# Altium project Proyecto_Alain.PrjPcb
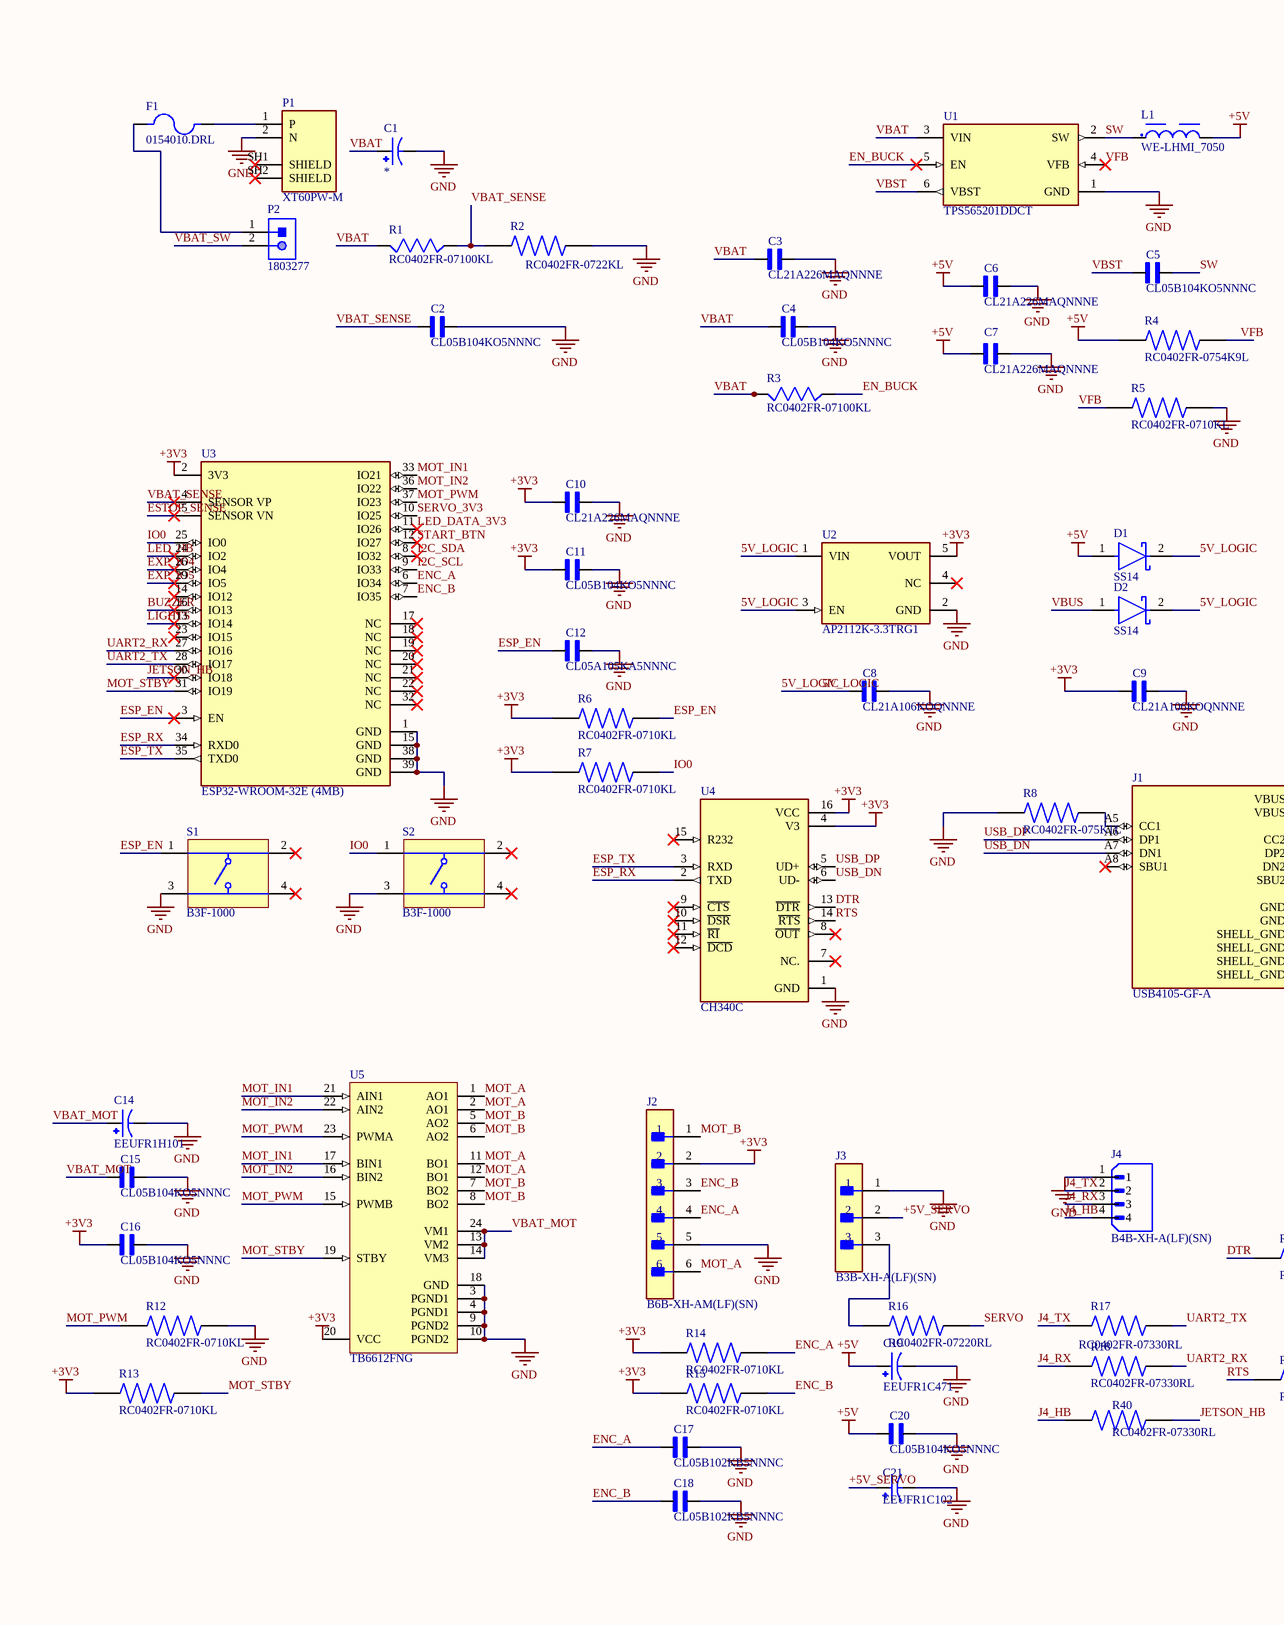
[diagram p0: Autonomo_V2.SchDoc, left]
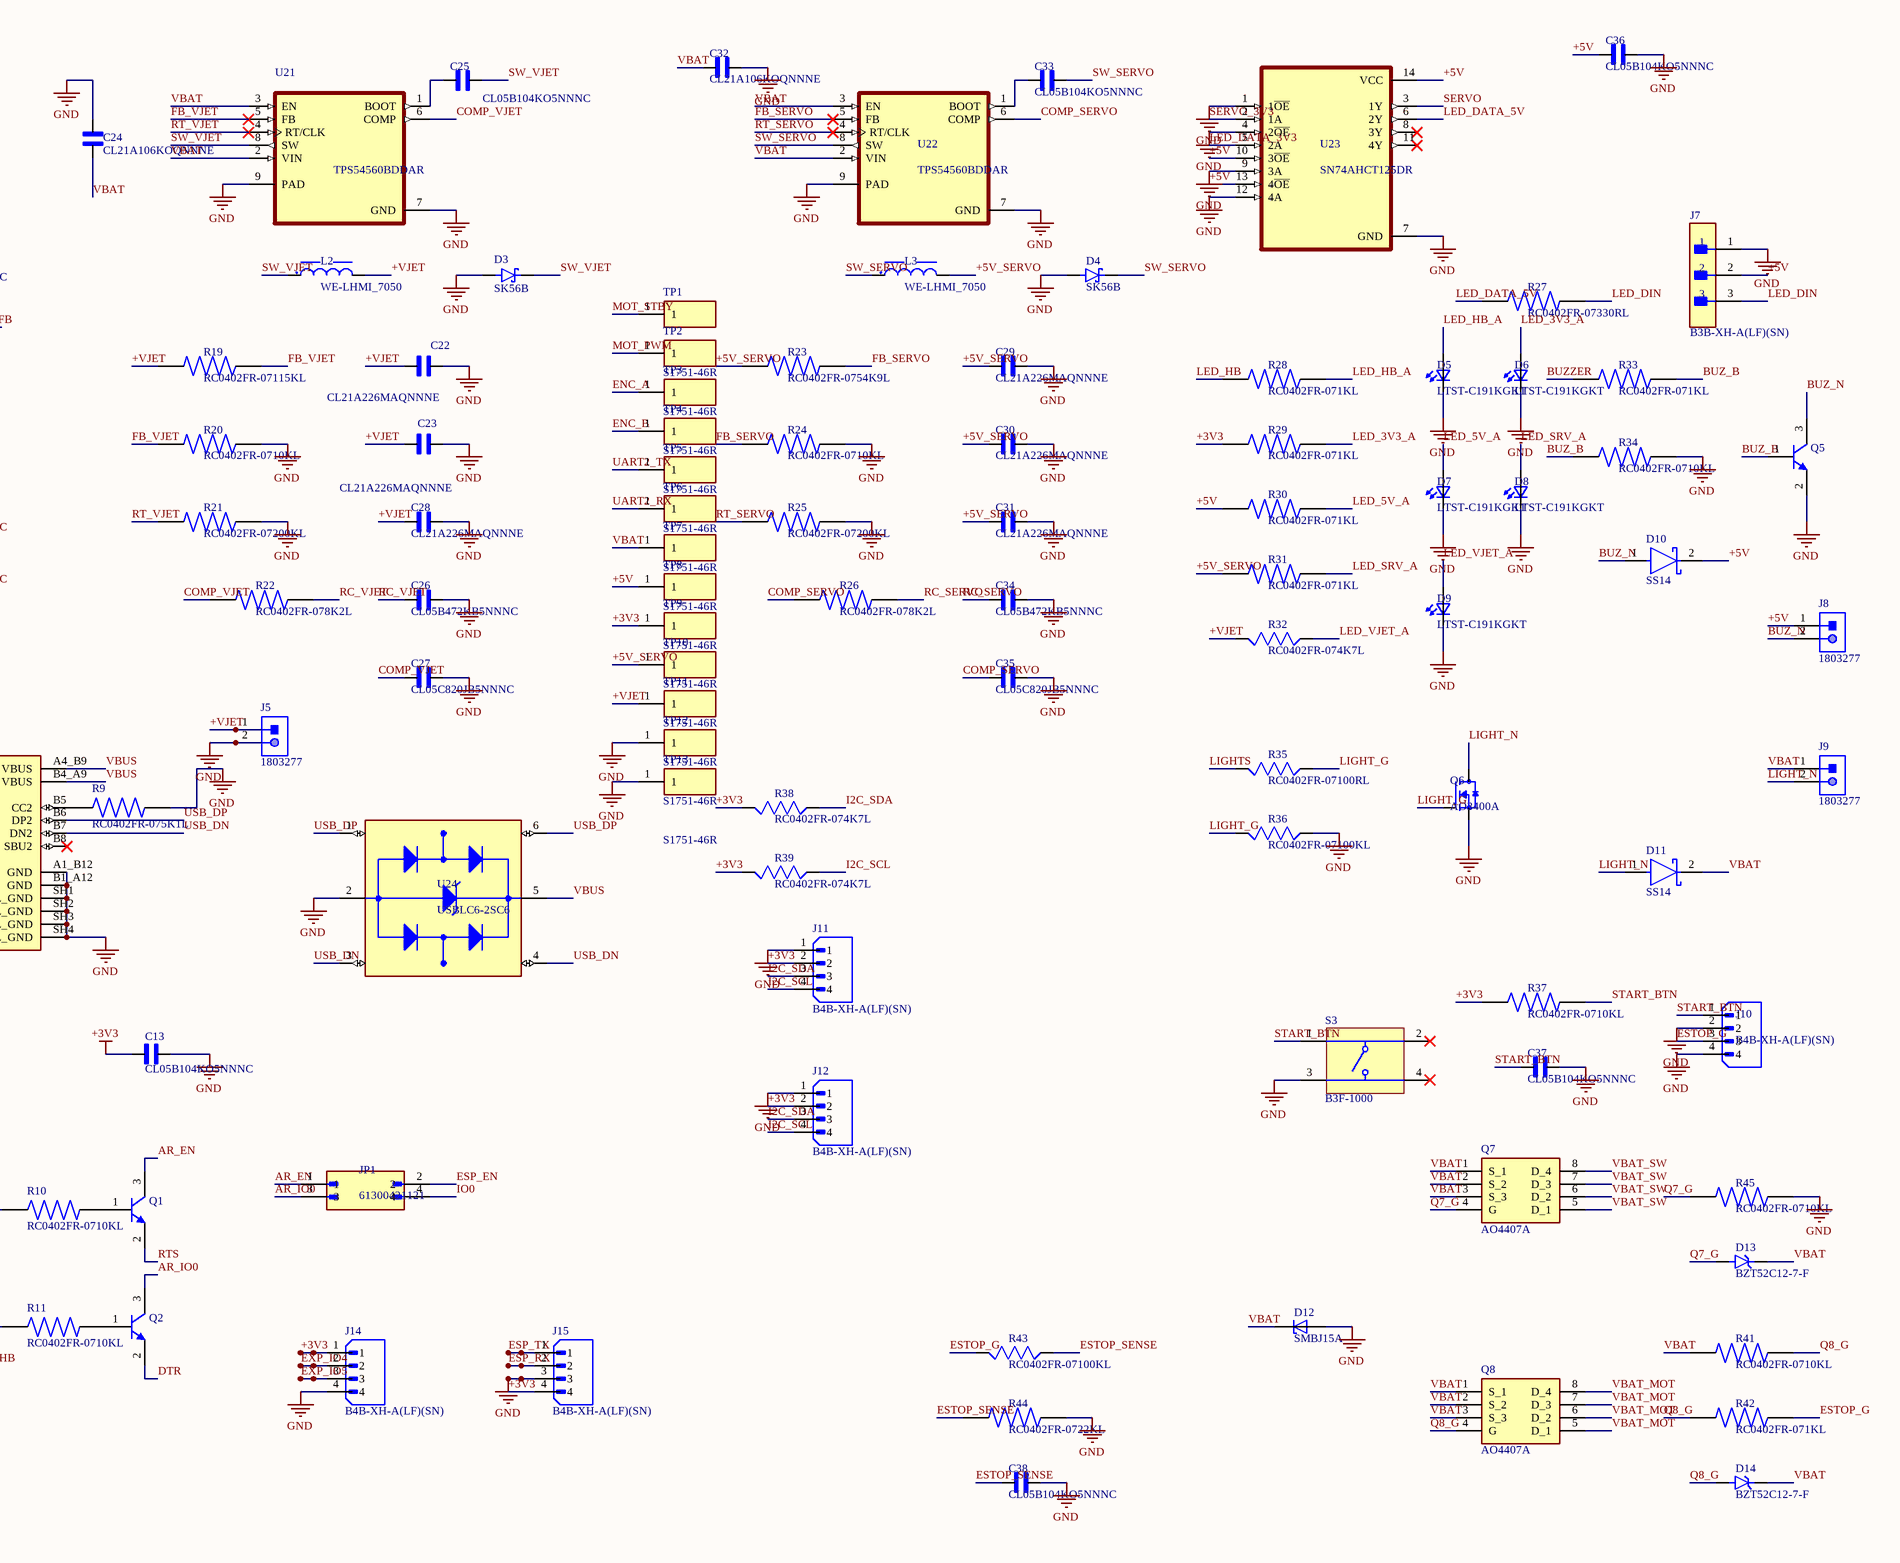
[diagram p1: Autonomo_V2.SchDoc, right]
1 sheet, 148 parts. Net scope: global (net labels, ports and power ports of the same name join across sheets).
Board file: Autonomo_V2.PcbDoc

## Sheet Autonomo_V2.SchDoc
size 609 x 304 mm; SheetNumber: 1; SheetTotal: 1

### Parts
C1  EEUFR1H471  [CAPPRD500W60D1250H2000]  (value not drawn)
C2  CL05B104KO5NNNC  [CAPC1005X55N]
C3  CL21A226MAQNNNE  [CAPC2012X140N]
C4  CL05B104KO5NNNC  [CAPC1005X55N]
C5  CL05B104KO5NNNC  [CAPC1005X55N]
C6  CL21A226MAQNNNE  [CAPC2012X140N]
C7  CL21A226MAQNNNE  [CAPC2012X140N]
C8  CL21A106KOQNNNE  [CAPC2012X140N]
C9  CL21A106KOQNNNE  [CAPC2012X140N]
C10  CL21A226MAQNNNE  [CAPC2012X140N]
C11  CL05B104KO5NNNC  [CAPC1005X55N]
C12  CL05A105KA5NNNC  [CAPC1005X55N]
C13  CL05B104KO5NNNC  [CAPC1005X55N]
C14  EEUFR1H101  [CAPPRD350W60D800H1150]
C15  CL05B104KO5NNNC  [CAPC1005X55N]
C16  CL05B104KO5NNNC  [CAPC1005X55N]
C17  CL05B102KB5NNNC  [CAPC1005X55N]
C18  CL05B102KB5NNNC  [CAPC1005X55N]
C19  EEUFR1C471  [CAPPRD350W60D800H1150]
C20  CL05B104KO5NNNC  [CAPC1005X55N]
C21  EEUFR1C102  [CAPPRD500W60D1000H1600]
C22  CL21A226MAQNNNE  [CAPC2012X140N]
C23  CL21A226MAQNNNE  [CAPC2012X140N]
C24  CL21A106KOQNNNE  [CAPC2012X140N]
C25  CL05B104KO5NNNC  [CAPC1005X55N]
C26  CL05B472KB5NNNC  [CAPC1005X55N]
C27  CL05C820JB5NNNC  [CAPC1005X55N]
C28  CL21A226MAQNNNE  [CAPC2012X140N]
C29  CL21A226MAQNNNE  [CAPC2012X140N]
C30  CL21A226MAQNNNE  [CAPC2012X140N]
C31  CL21A226MAQNNNE  [CAPC2012X140N]
C32  CL21A106KOQNNNE  [CAPC2012X140N]
C33  CL05B104KO5NNNC  [CAPC1005X55N]
C34  CL05B472KB5NNNC  [CAPC1005X55N]
C35  CL05C820JB5NNNC  [CAPC1005X55N]
C36  CL05B104KO5NNNC  [CAPC1005X55N]
C37  CL05B104KO5NNNC  [CAPC1005X55N]
C38  CL05B104KO5NNNC  [CAPC1005X55N]
D1  SS14  [FP-403AE-MFG]
D2  SS14  [FP-403AE-MFG]
D3  SK56B  [DIO_SK56B]
D4  SK56B  [DIO_SK56B]
D5  LTST-C191KGKT  [0603]
D6  LTST-C191KGKT  [0603]
D7  LTST-C191KGKT  [0603]
D8  LTST-C191KGKT  [0603]
D9  LTST-C191KGKT  [0603]
D10  SS14  [FP-403AE-MFG]
D11  SS14  [FP-403AE-MFG]
D12  SMBJ15A  [DIOM4336X265N]
D13  BZT52C12-7-F  [DIO_BZT52C12-7-F]
D14  BZT52C12-7-F  [DIO_BZT52C12-7-F]
F1  0154010.DRL  [FUSE_0154010.DRL]
J1  USB4105-GF-A  [GCT_USB4105-GF-A]
J2  B6B-XH-AM(LF)(SN)  [FP-B6B-XH-AM_LF_SN-MFG]
J3  B3B-XH-A(LF)(SN)  [FP-B3B-XH-A_LF_SN-MFG]
J4  B4B-XH-A(LF)(SN)  [JST_B4B-XH-A(LF)(SN)]
J5  1803277  [PHOE-1803277_V]
J7  B3B-XH-A(LF)(SN)  [FP-B3B-XH-A_LF_SN-MFG]
J8  1803277  [PHOE-1803277_V]
J9  1803277  [PHOE-1803277_V]
J10  B4B-XH-A(LF)(SN)  [JST_B4B-XH-A(LF)(SN)]
J11  B4B-XH-A(LF)(SN)  [JST_B4B-XH-A(LF)(SN)]
J12  B4B-XH-A(LF)(SN)  [JST_B4B-XH-A(LF)(SN)]
J14  B4B-XH-A(LF)(SN)  [JST_B4B-XH-A(LF)(SN)]
J15  B4B-XH-A(LF)(SN)  [JST_B4B-XH-A(LF)(SN)]
JP1  61300421121  [WURTH_61300421121]
L1  WE-LHMI_7050  [WE-LHMI_7050]
L2  WE-LHMI_7050  [WE-LHMI_7050]
L3  WE-LHMI_7050  [WE-LHMI_7050]
P1  XT60PW-M  [AMASS_XT60PW-M]
P2  1803277  [PHOE-1803277_V]
Q1  MMBT3904  [FAIR-SOT23-3_V]  (value not drawn)
Q2  MMBT3904  [FAIR-SOT23-3_V]  (value not drawn)
Q5  MMBT3904  [FAIR-SOT23-3_V]  (value not drawn)
Q6  AO3400A  [SOT95P280X125-3N]
Q7  AO4407A  [SOIC127P600X175-8N]
Q8  AO4407A  [SOIC127P600X175-8N]
R1  RC0402FR-07100KL  [RESC1005X40]
R2  RC0402FR-0722KL  [RESC1005X40N]
R3  RC0402FR-07100KL  [RESC1005X40]
R4  RC0402FR-0754K9L  [RESC1005X40N]
R5  RC0402FR-0710KL  [RESC1005X40N]
R6  RC0402FR-0710KL  [RESC1005X40N]
R7  RC0402FR-0710KL  [RESC1005X40N]
R8  RC0402FR-075K1L  [RESC1005X40N]
R9  RC0402FR-075K1L  [RESC1005X40N]
R10  RC0402FR-0710KL  [RESC1005X40N]
R11  RC0402FR-0710KL  [RESC1005X40N]
R12  RC0402FR-0710KL  [RESC1005X40N]
R13  RC0402FR-0710KL  [RESC1005X40N]
R14  RC0402FR-0710KL  [RESC1005X40N]
R15  RC0402FR-0710KL  [RESC1005X40N]
R16  RC0402FR-07220RL  [RESC1005X40N]
R17  RC0402FR-07330RL  [RESC1005X40N]
R18  RC0402FR-07330RL  [RESC1005X40N]
R19  RC0402FR-07115KL  [RESC1005X40N]
R20  RC0402FR-0710KL  [RESC1005X40N]
R21  RC0402FR-07200KL  [RESC1005X40N]
R22  RC0402FR-078K2L  [RESC1005X40N]
R23  RC0402FR-0754K9L  [RESC1005X40N]
R24  RC0402FR-0710KL  [RESC1005X40N]
R25  RC0402FR-07200KL  [RESC1005X40N]
R26  RC0402FR-078K2L  [RESC1005X40N]
R27  RC0402FR-07330RL  [RESC1005X40N]
R28  RC0402FR-071KL  [RESC1005X40N]
R29  RC0402FR-071KL  [RESC1005X40N]
R30  RC0402FR-071KL  [RESC1005X40N]
R31  RC0402FR-071KL  [RESC1005X40N]
R32  RC0402FR-074K7L  [RESC1005X40]
R33  RC0402FR-071KL  [RESC1005X40N]
R34  RC0402FR-0710KL  [RESC1005X40N]
R35  RC0402FR-07100RL  [RESC1005X40]
R36  RC0402FR-07100KL  [RESC1005X40]
R37  RC0402FR-0710KL  [RESC1005X40N]
R38  RC0402FR-074K7L  [RESC1005X40]
R39  RC0402FR-074K7L  [RESC1005X40]
R40  RC0402FR-07330RL  [RESC1005X40N]
R41  RC0402FR-0710KL  [RESC1005X40N]
R42  RC0402FR-071KL  [RESC1005X40N]
R43  RC0402FR-07100KL  [RESC1005X40]
R44  RC0402FR-0722KL  [RESC1005X40N]
R45  RC0402FR-0710KL  [RESC1005X40N]
S1  B3F-1000  [OMRON-B3F-1000-4_V]
S2  B3F-1000  [OMRON-B3F-1000-4_V]
S3  B3F-1000  [OMRON-B3F-1000-4_V]
TP1  S1751-46R  [S175146R]
TP2  S1751-46R  [S175146R]
TP3  S1751-46R  [S175146R]
TP4  S1751-46R  [S175146R]
TP5  S1751-46R  [S175146R]
TP6  S1751-46R  [S175146R]
TP7  S1751-46R  [S175146R]
TP8  S1751-46R  [S175146R]
TP9  S1751-46R  [S175146R]
TP10  S1751-46R  [S175146R]
TP11  S1751-46R  [S175146R]
TP12  S1751-46R  [S175146R]
TP13  S1751-46R  [S175146R]
U1  TPS565201DDCT  [FP-DDC0006A-IPC_B]
U2  AP2112K-3.3TRG1  [FP-SOT25-IPC_A]
U3  ESP32-WROOM-32E (4MB)  [FP-ESP32-WROOM-32E_4MB-MFG]
U4  CH340C  [SOIC127P600X180-16N]
U5  TB6612FNG  [TOSH-SSOP-24_M]
U21  TPS54560BDDAR  [VREG_LM5017MR/NOPB]
U22  TPS54560BDDAR  [VREG_LM5017MR/NOPB]
U23  SN74AHCT125DR  [SOIC127P600X175-14N]
U24  USBLC6-2SC6  [SOT95P280X145-6N]

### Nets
+3V3: C9.1 C10.1 C11.1 C13.1 C16.1 J2.2 J11.2 J12.2 J14.1 J15.4 R6.1 R7.1 R13.1 R14.1 R15.1 R29.1 R37.1 R38.1 R39.1 TP9.1 U2.5(VOUT) U3.2(3V3) U4.4(V3) U4.16(VCC) U5.20(VCC)
+5V: C6.1 C7.1 C19.P C20.1 C36.1 D1.1(A) D10.2(C) J7.2 J8.1 L1.2 R4.1 R30.1 TP8.1 U23.10(3~{OE}) U23.13(4~{OE}) U23.14(VCC)
GND: C1.N C2.2 C3.2 C4.2 C6.2 C7.2 C8.2 C9.2 C10.2 C11.2 C12.2 C13.2 C14.N C15.2 C16.2 C17.2 C18.2 C19.N C20.2 C21.N C22.2 C23.2 C24.2 C26.2 C27.2 C28.2 C29.2 C30.2 C31.2 C32.2 C34.2 C35.2 C36.2 C37.2 C38.2 D3.A D4.A D5.1(K2) D6.1(K2) D7.1(K2) D8.1(K2) D9.1(K2) D12.A J1.A1_B12(GND) J1.B1_A12(GND) J1.SH1(SHELL_GND) J1.SH2(SHELL_GND) J1.SH3(SHELL_GND) J1.SH4(SHELL_GND) J2.5 J3.1 J4.1 J5.2 J7.1 J10.2 J10.4 J11.1 J12.1 J14.4 J15.3 P1.2(N) Q5.2(E) Q6.2(S) R2.2 R5.2 R8.2 R9.2 R12.2 R20.2 R21.2 R24.2 R25.2 R34.2 R36.2 R44.2 R45.2 S1.3 S2.3 S3.3 TP12.1 TP13.1 U1.1(GND) U2.2(GND) U3.1(GND) U3.15(GND) U3.38(GND) U3.39(GND) U4.1(GND) U5.3(PGND1) U5.4(PGND1) U5.9(PGND2) U5.10(PGND2) U5.18(GND) U21.7(GND) U21.9(PAD) U22.7(GND) U22.9(PAD) U23.1(1~{OE}) U23.4(2~{OE}) U23.7(GND) U23.9(3A) U23.12(4A) U24.2(GND)
5V_LOGIC: C8.1 D1.2(C) D2.2(C) U2.1(VIN) U2.3(EN)
+5V_SERVO: C21.P C29.1 C30.1 C31.1 J3.2 L3.2 R23.1 R31.1 TP10.1
+VJET: C22.1 C23.1 C28.1 J5.1 L2.2 R19.1 R32.1 TP11.1
AR_EN: JP1.1 Q1.3(C)
AR_IO0: JP1.3 Q2.3(C)
BUZ_B: Q5.1(B) R33.2 R34.1
BUZ_N: D10.1(A) J8.2 Q5.3(C)
BUZZER: R33.1 U3.16(IO13)
COMP_SERVO: C35.1 R26.1 U22.6(COMP)
COMP_VJET: C27.1 R22.1 U21.6(COMP)
DTR: Q2.2(E) R10.1 U4.13(~{DTR})
EN_BUCK: R3.2 U1.5(EN)
ENC_A: C17.1 J2.4 R14.2 TP3.1 U3.6(IO34)
ENC_B: C18.1 J2.3 R15.2 TP4.1 U3.7(IO35)
ESP_EN: C12.1 JP1.2 R6.2 S1.1 U3.3(EN)
ESP_RX: J15.2 U3.34(RXD0) U4.2(TXD)
ESP_TX: J15.1 U3.35(TXD0) U4.3(RXD)
ESTOP_G: J10.3 R42.2 R43.1
ESTOP_SENSE: C38.1 R43.2 R44.1 U3.5(SENSOR_VN)
EXP_IO4: J14.2 U3.26(IO4)
EXP_IO5: J14.3 U3.29(IO5)
FB_SERVO: R23.2 R24.1 U22.5(FB)
FB_VJET: R19.2 R20.1 U21.5(FB)
I2C_SCL: J11.4 J12.4 R39.2 U3.9(IO33)
I2C_SDA: J11.3 J12.3 R38.2 U3.8(IO32)
IO0: JP1.4 R7.2 S2.1 U3.25(IO0)
J4_HB: J4.4 R40.1
J4_RX: J4.3 R18.1
J4_TX: J4.2 R17.1
JETSON_HB: R40.2 U3.30(IO18)
LED_3V3_A: D6.2(A2) R29.2
LED_5V_A: D7.2(A2) R30.2
LED_DATA_3V3: U3.11(IO26) U23.5(2A)
LED_DATA_5V: R27.1 U23.6(2Y)
LED_DIN: J7.3 R27.2
LED_HB: R28.1 U3.24(IO2)
LED_HB_A: D5.2(A2) R28.2
LED_SRV_A: D8.2(A2) R31.2
LED_VJET_A: D9.2(A2) R32.2
LIGHT_G: Q6.1(G) R35.2 R36.1
LIGHT_N: D11.1(A) J9.2 Q6.3(D)
LIGHTS: R35.1 U3.13(IO14)
MOT_A: J2.6 U5.1(AO1) U5.2(AO1) U5.11(BO1) U5.12(BO1)
MOT_B: J2.1 U5.5(AO2) U5.6(AO2) U5.7(BO2) U5.8(BO2)
MOT_IN1: U3.33(IO21) U5.17(BIN1) U5.21(AIN1)
MOT_IN2: U3.36(IO22) U5.16(BIN2) U5.22(AIN2)
MOT_PWM: R12.1 TP2.1 U3.37(IO23) U5.15(PWMB) U5.23(PWMA)
MOT_STBY: R13.2 TP1.1 U3.31(IO19) U5.19(STBY)
Q7_G: D13.2(A) Q7.4(G) R45.1
Q8_G: D14.2(A) Q8.4(G) R41.2 R42.1
RC_SERVO: C34.1 R26.2
RC_VJET: C26.1 R22.2
RT_SERVO: R25.1 U22.4(RT/CLK)
RT_VJET: R21.1 U21.4(RT/CLK)
RTS: Q1.2(E) R11.1 U4.14(~{RTS})
SERVO: R16.2 U23.3(1Y)
SERVO_3V3: U3.10(IO25) U23.2(1A)
START_BTN: C37.1 J10.1 R37.2 S3.1 U3.12(IO27)
SW: C5.2 L1.1 U1.2(SW)
SW_SERVO: C33.2 D4.C(K) L3.1 U22.8(SW)
SW_VJET: C25.2 D3.C(K) L2.1 U21.8(SW)
UART2_RX: R18.2 TP6.1 U3.27(IO16)
UART2_TX: R17.2 TP5.1 U3.28(IO17)
USB_DN: J1.A7(DN1) J1.B7(DN2) U4.6(UD-) U24.3(I/O2_IN) U24.4(I/O2_OUT)
USB_DP: J1.A6(DP1) J1.B6(DP2) U4.5(UD+) U24.1(I/O1_IN) U24.6(I/O1_OUT)
VBAT: C1.P C3.1 C4.1 C24.1 C32.1 D11.2(C) D12.C D13.1(K) D14.1(K) J9.1 Q7.1(S_1) Q7.2(S_2) Q7.3(S_3) Q8.1(S_1) Q8.2(S_2) Q8.3(S_3) R1.1 R3.1 R41.1 TP7.1 U1.3(VIN) U21.2(VIN) U21.3(EN) U22.2(VIN) U22.3(EN)
VBAT_MOT: C14.P C15.1 Q8.5(D_1) Q8.6(D_2) Q8.7(D_3) Q8.8(D_4) U5.13(VM2) U5.14(VM3) U5.24(VM1)
VBAT_SENSE: C2.1 R1.2 R2.1 U3.4(SENSOR_VP)
VBAT_SW: P2.2 Q7.5(D_1) Q7.6(D_2) Q7.7(D_3) Q7.8(D_4)
VBST: C5.1 U1.6(VBST)
VBUS: D2.1(A) J1.A4_B9(VBUS) J1.B4_A9(VBUS) U24.5(VBUS)
VFB: R4.2 R5.1 U1.4(VFB)
NetC25_1: C25.1 U21.1(BOOT)
NetC33_1: C33.1 U22.1(BOOT)
NetF1_1: F1.1 P1.1(P)
NetF1_2: F1.2 P2.1
NetJ1_A5: J1.A5(CC1) R8.1
NetJ1_B5: J1.B5(CC2) R9.1
NetJ3_3: J3.3 R16.1
NetQ1_1: Q1.1(B) R10.2
NetQ2_1: Q2.1(B) R11.2

Not connected (* = marked no-connect by the designer): J1 A8(SBU1)* B8(SBU2)*; P1 SH1(SHIELD)* SH2(SHIELD)*; S1 2* 4*; S2 2* 4*; S3 2* 4*; U2 4(NC)*; U3 14(IO12)* 17(NC)* 18(NC)* 19(NC)* 20(NC)* 21(NC)* 22(NC)* 23(IO15)* 32(NC)*; U4 7(NC.)* 8(~{OUT})* 9(~{CTS})* 10(~{DSR})* 11(~{RI})* 12(~{DCD})* 15(R232)*; U23 8(3Y)* 11(4Y)*

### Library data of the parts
C1 = EEUFR1H471: 470ÂµF 50V Aluminum Electrolytic Capacitors Radial, Can 10000 Hrs @ 105Â°C; MF: Panasonic
C2 C4 C5 C11 C13 C15 C16 C20 C25 C33 C36-C38 = CL05B104KO5NNNC: 0.1 ÂµF Â±10% 16V Ceramic Capacitor X7R 0402 (1005 Metric); MF: Samsung
C3 C6 C7 C10 C22 C23 C28-C31 = CL21A226MAQNNNE: MF: {'manufacturer': u'Samsung Electro-Mechanics'}
C12 = CL05A105KA5NNNC: Multilayer Ceramic Capacitors MLCC - SMD/SMT 1uF+/-10% 25V X5R 1005; MF: Samsung Electro-Mechanics
C14 = EEUFR1H101: 100F 50V Aluminum Electrolytic Capacitors Radial, Can 6000 Hrs @ 105C; MP: EEU-FR1H101; MF: Panasonic
C17 C18 = CL05B102KB5NNNC: 1000 pF Â±10% 50V Ceramic Capacitor X7R 0402 (1005 Metric); MF: Samsung Electro-Mechanics
C19 = EEUFR1C471: Cap Aluminum Lytic 470uF 16V 20% (8 X 11.5mm) Radial 3.5mm 950mA 6000h 105C Bulk; MF: Panasonic
C21 = EEUFR1C102: Tutup Aluminium Lytic 1000uF 16V 20% (10 X 16mm) Radial 5mm 1790mA 8000h 105C Massal; MF: Panasonic Electronic; MP: EEU-FR1C102
C26 C34 = CL05B472KB5NNNC: 4700 pF Â±10% 50V Ceramic Capacitor X7R 0402 (1005 Metric); MF: Samsung
D1 D2 D10 D11 = CMP-2000-04943-2: DIODE SCHOTTKY 40V 1A SMA; Manufacturer: ON Semiconductor; Peak Reverse Current: 0.2mA; Max Junction Temp: +125°C; Standoff Height: 0.05mm; Max Surge Forward Current: 40A
D3 D4 = SK56B: 5A, 60V, Schottky Rectifier; MF: Taiwan Semiconductor
D5-D9 = LTST-C191KGKT: Green 571nm LED Indication - Discrete 2V 0603 (1608 Metric); MF: Lite-On Inc.
D12 = SMBJ15A: 600W, 17.6V, 5%, Unidirectional, TVS; MF: Taiwan Semiconductor
D13 D14 = BZT52C12-7-F: Zener Diode 12V 5.3% 500mW SOD123 ¦ Diodes Inc BZT52C12-7-F; MF: Diodes Inc.
F1 = 0154010.DRL: 10 A 125 V AC 125 V DC Fuse Board Mount (Cartridge Style Excluded) Requires Holder, Surface Mount 2-SMD, Square End Block with Holder; MF: Littelfuse Inc.
J1 = USB4105-GF-A: MF: {'manufacturer': u'GCT'}
J2 = CMP-17439-000167-1: CONN HEADER VERT 6POS 2.5MM; Shape: Straight; Current Rating: 3A; Mated Stacking Heights: 9.8mm; Number of Positions: 6; Voltage Rating: 250V
J3 J7 = CMP-17439-000014-3: CONN HEADER VERT 3POS 2.5MM; Max Voltage Rating (DC): 250V; Number of Positions: 3; Current Rating: 3A; Gender: Male; Wire/Cable Gauge: 22AWG; Contact Resistance: 20mR; Insulation Resistance: 1GR
J4 J10-J12 J14 J15 = B4B-XH-A(LF)(SN): Connector Header Through Hole 4 position 0.098 (2.50mm); MF: JST Sales
J5 J8 J9 P2 = CMP-002-00014-2: Male Header, Pitch 3.81 mm, 1 x 2 Position, Height 7.25 mm, Tail Length 3.4 mm, RoHS, Bulk; Manufacturer: Phoenix Contact; Voltage Rating: 160V; Current Rating: 8A; Rows: 1
JP1 = 61300421121: Connector Header Through Hole 4 position 0.100 (2.54mm); MF: WÃ¼rth Elektronik
L1 L3 = WE-LHMI_7050: 4.7ÂµH Shielded Molded Inductor 5A 30.8mOhm Max Nonstandard; MF: WÃ¼rth Elektronik; MP: 74437349047
L2 = WE-LHMI_7050: 4.7ÂµH Shielded Molded Inductor 5A 30.8mOhm Max Nonstandard; MF: WÃ¼rth Elektronik; MP: 74437349033
P1 = XT60PW-M: Socket, DC supply, male, PIN: 2; MF: AMASS
Q1 Q2 Q5 = CMP-1670-00008-1: NPN General Purpose Amplifier, 40 V, 0.2 A, -55 to 150 degC, 3-Pin SOT23, RoHS, Tape and Reel; Tolerance: 30ppm; Capacitance: 1.8E-11 f; Frequency: 12.288 MHz; ESR: 40 Ohm; Load Capacitance: 18 pF
Q6 = AO3400A: N-Channel 30 V 5.8A (Ta) 1.4W (Ta) Surface Mount SOT-23; MF: UMW
Q7 Q8 = AO4407A: 30V P-Channel MOSFET; Manufacturer_Name: Alpha & Omega Semiconductors; Geometry.Height: 1.75mm
R1 R3 R36 R43 = RC0402FR-07100KL: 100 kOhms Â±1% 0.063W, 1/16W Chip Resistor 0402 (1005 Metric) Moisture Resistant Thick Film; MF: Yageo
R2 R44 = RC0402FR-0722KL: 22 kOhms Â±1% 0.063W, 1/16W Chip Resistor 0402 (1005 Metric) Moisture Resistant Thick Film; MF: Yageo
R4 R23 = RC0402FR-0754K9L: 54.9 kOhms Â±1% 0.063W, 1/16W Chip Resistor 0402 (1005 Metric) Moisture Resistant Thick Film; MF: Yageo
R5-R7 R10-R15 R20 R24 R34 R37 R41 R45 = RC0402FR-0710KL: 10 kOhms Â±1% 0.063W, 1/16W Chip Resistor 0402 (1005 Metric) Moisture Resistant Thick Film; MF: Yageo Corporation
R8 R9 = RC0402FR-075K1L: 5.1 kOhms Â±1% 0.063W, 1/16W Chip Resistor 0402 (1005 Metric) Moisture Resistant Thick Film; MF: Yageo
R16 = RC0402FR-07220RL: 220 Ohms Â±1% 0.063W, 1/16W Chip Resistor 0402 (1005 Metric) Moisture Resistant Thick Film; MF: Yageo
R17 R18 R27 R40 = RC0402FR-07330RL: 330 Ohms Â±1% 0.063W, 1/16W Chip Resistor 0402 (1005 Metric) Moisture Resistant Thick Film; MF: Yageo
R19 = RC0402FR-07115KL: 115 kOhms Â±1% 0.063W, 1/16W Chip Resistor 0402 (1005 Metric) Moisture Resistant Thick Film; MF: Yageo
R21 R25 = RC0402FR-07200KL: 200 kOhms Â±1% 0.063W, 1/16W Chip Resistor 0402 (1005 Metric) Moisture Resistant Thick Film; MF: Yageo
R22 R26 = RC0402FR-078K2L: 8.2 kOhms Â±1% 0.063W, 1/16W Chip Resistor 0402 (1005 Metric) Moisture Resistant Thick Film; MF: Yageo
R28-R31 R33 R42 = RC0402FR-071KL: 1 kOhms Â±1% 0.063W, 1/16W Chip Resistor 0402 (1005 Metric) Moisture Resistant Thick Film; MF: Yageo Corporation; MP: RC0402FR071KL
R32 R38 R39 = RC0402FR-074K7L: 4.7 kOhms Â±1% 0.063W, 1/16W Chip Resistor 0402 (1005 Metric) Moisture Resistant Thick Film; MF: Yageo
R35 = RC0402FR-07100RL: 100 Ohms Â±1% 0.063W, 1/16W Chip Resistor 0402 (1005 Metric) Moisture Resistant Thick Film; MF: Yageo
S1-S3 = CMP-011-00004-2: Tactile Switch, SPST-NO, 0.05 A, 24 V, -25 to 70 degC, 4-Pin THD, RoHS, Bulk; Manufacturer: Omron Electronic Components; Throw Configuration: SPST; Max Contact Resistance: 100mohm; Resistance: 0.1Ohm; Max Current Rating: 50mA; Voltage Rating: 24V; Operating Force: 100gf
TP1-TP13 = S1751-46R: Hardware: SMT Test Point 1.63x3.25mm 2mm high (T+R); Manufacturer_Name: Harwin
U1 = CMP-04918-000464-1: IC REG BUCK ADJ 5A TSOT23-6; Synchronous Rectifier: Yes; Min Output Voltage: 600mV; Output Type: Adjustable; Max Input Voltage: 17V; Min Input Voltage: 4.5V; Switching Frequency: 500kHz; Number of Outputs: 1; Max Output Voltage: 7V; Output Configuration: Positive
U2 = CMP-12756-000035-1: IC REG LINEAR 3.3V 600MA SOT25; Number of Regulators: 1; Output Type: Fixed; Polarity: Positive; Min Input Voltage: 2.5V; Max Input Voltage: 6V; Accuracy: 1.5%; Quiescent Current: 55uA; Dropout Voltage: 250mV
U3 = CMP-194065-000026-1: RX TXRX MOD WIFI TRACE ANT SMD
U4 = CH340C: USB to serial chip CH340; MF: WCH
U5 = CMP-1773-00001-1: Driver IC for Dual DC Motor, 15 V, -20 to 85 degC, 24-Pin SSOP, RoHS, Tape and Reel; Elements: 2; Max Power Dissipation: 200 mW; Max Surge Current: 100 mA; Element Configuration: Common Cathode; Case\Package: TO-236-3; Forward Voltage: 1 V; Peak Reverse Current: 0.1 uA; Forward Current: 70 mA; Recovery Time: 5 ns
U21 U22 = TPS54560BDDAR: 4.5-V to 60-V input, 5-A, step-down DC-DC converter with Eco-modeâ„¢; MF: Texas Instruments
U23 = SN74AHCT125DR: 4-ch, 4.5-V to 5.5-V buffers with TTL-compatible CMOS inputs and 3-state outputs; MF: Texas Instruments
U24 = USBLC6-2SC6: 17V Clamp 5A (8/20Âµs) Ipp Tvs Diode Surface Mount SOT-23-6; MF: STMicroelectronics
